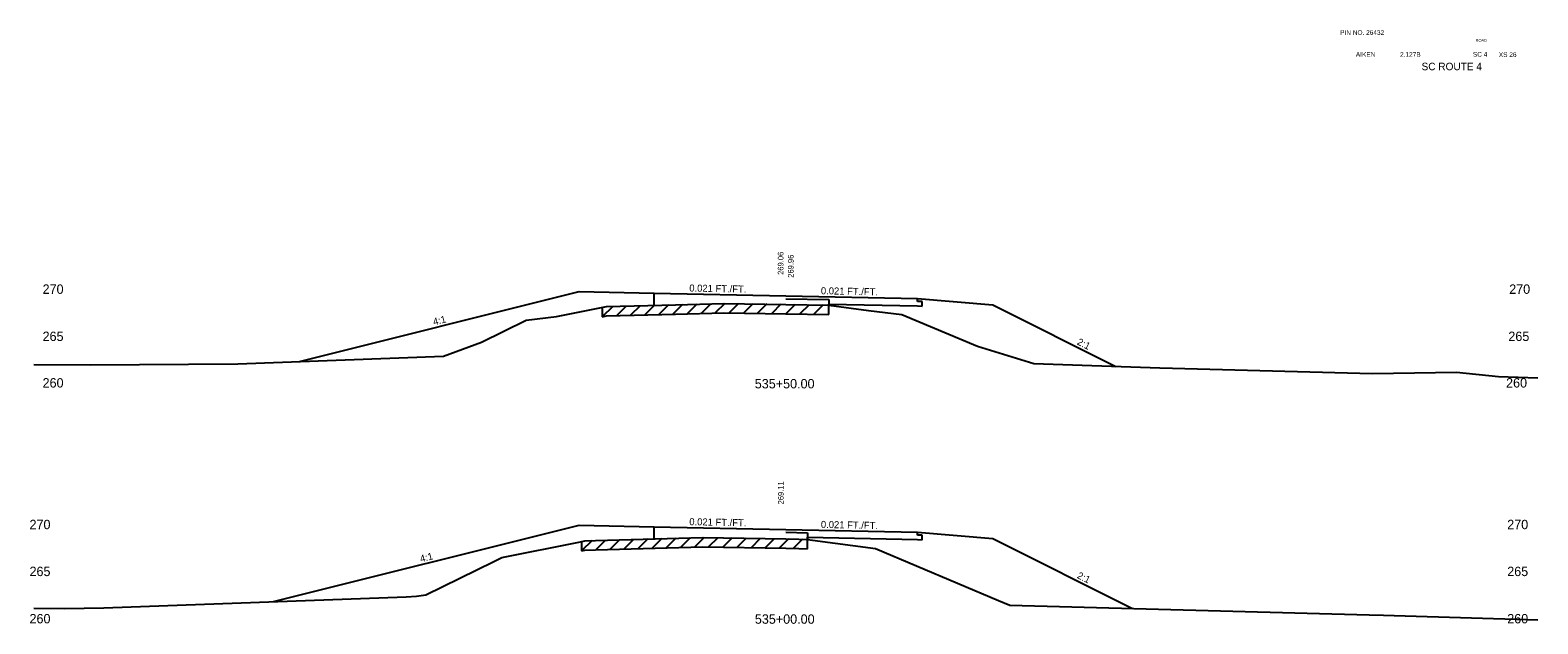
# Model space of a CAD drawing. Extents: x 883 to 1160, y 1002 to 4323.
# Drawn here: x 999.6 to 1160, y 3915.1 to 3978.2 of the extents above; entities that cross this region are included whole.
import ezdxf

# ---------------------------------------------------------------- set-up
doc = ezdxf.new("R2010")
doc.units = 0
for name, color, linetype in [('Level 1', 7, 'Continuous'), ('Level 10', 7, 'Continuous'), ('Level 11', 7, 'Continuous'), ('Level 12', 7, 'Continuous'), ('Level 3', 7, 'Continuous'), ('Level 32', 7, 'Continuous'), ('Level 53', 7, 'Continuous'), ('Level 59', 7, 'Continuous'), ('Level 6', 7, 'Continuous'), ('Level 60', 7, 'Continuous'), ('Level 61', 7, 'Continuous'), ('Level 7', 7, 'Continuous')]:
    doc.layers.add(name, color=color, linetype=linetype)

msp = doc.modelspace()

# ---------------------------------------------------------------- linework, layer by layer
at = {"layer": 'Level 11'}
for p, q in [((1066, 3948.96), (1066, 3950.26)), ((1094, 3949.37), (1094, 3949.67)), ((1094.5, 3949.36), (1094, 3949.37)), ((1094.5, 3948.88), (1094.5, 3949.36)), ((1094, 3948.89), (1094.5, 3948.88)), ((1066, 3924.12), (1066, 3925.4)), ((1094, 3924.52), (1094, 3924.82)), ((1094.5, 3924.5), (1094, 3924.52)), ((1094, 3924.04), (1094.5, 3924.02)), ((1094.5, 3924.02), (1094.5, 3924.5))]:
    msp.add_line(p, q, dxfattribs=at)
at = {"layer": 'Level 12'}
for p, q in [((1084.57, 3948.99), (1084.57, 3949.09)), ((1084.57, 3949.09), (1094, 3948.89)), ((1082.31, 3924.06), (1082.31, 3924.28)), ((1082.31, 3924.28), (1094, 3924.04))]:
    msp.add_line(p, q, dxfattribs=at)
at = {"layer": 'Level 53'}
for p, q in [((1080, 3949.66), (1084.57, 3949.57)), ((1084.57, 3949.57), (1084.57, 3948.99)), ((1080, 3924.81), (1082.31, 3924.76)), ((1082.31, 3924.76), (1082.31, 3924.06))]:
    msp.add_line(p, q, dxfattribs=at)
at = {"layer": 'Level 59'}
for p, q in [((1066, 3950.26), (1080, 3949.96)), ((1080, 3949.96), (1094, 3949.67)), ((1066, 3925.4), (1080, 3925.11)), ((1080, 3925.11), (1094, 3924.82))]:
    msp.add_line(p, q, dxfattribs=at)
at = {"layer": 'Level 6'}
for p, q in [((1058, 3950.42), (1066, 3950.26)), ((1094, 3949.67), (1102, 3949.01)), ((1058, 3925.56), (1066, 3925.4)), ((1094, 3924.82), (1102, 3924.15))]:
    msp.add_line(p, q, dxfattribs=at)
at = {"layer": 'Level 60'}
for p, q in [((1068.25, 3949.02), (1073.41, 3949.17)), ((1073.41, 3949.17), (1080, 3949.06)), ((1052.38, 3947.37), (1055.59, 3947.76)), ((1055.59, 3947.76), (1060.9, 3948.83)), ((1060.9, 3948.83), (1068.25, 3949.02)), ((1080, 3949.06), (1084.58, 3948.99)), ((1084.58, 3948.99), (1088.78, 3948.42)), ((1088.78, 3948.42), (1092.35, 3947.98)), ((1092.35, 3947.98), (1100.37, 3944.61)), ((1047.62, 3945.05), (1052.38, 3947.37)), ((1043.56, 3943.55), (1047.62, 3945.05)), ((1100.37, 3944.61), (1106.37, 3942.77)), ((1000, 3942.67), (1006, 3942.62)), ((1006, 3942.62), (1021.69, 3942.75)), ((1021.69, 3942.75), (1043.56, 3943.55)), ((1106.37, 3942.77), (1119.78, 3942.3)), ((1119.78, 3942.3), (1142.41, 3941.69)), ((1142.41, 3941.69), (1151.34, 3941.83)), ((1151.34, 3941.83), (1155.83, 3941.38)), ((1155.83, 3941.38), (1160, 3941.26)), ((1049.78, 3922.12), (1057.99, 3923.76)), ((1057.99, 3923.76), (1058.6, 3923.91)), ((1058.6, 3923.91), (1059.73, 3923.95)), ((1059.73, 3923.95), (1071.18, 3924.26)), ((1071.18, 3924.26), (1080, 3924.11)), ((1080, 3924.11), (1081.39, 3924.08)), ((1081.39, 3924.08), (1082.3, 3924.06)), ((1082.3, 3924.06), (1082.84, 3923.98)), ((1082.84, 3923.98), (1089.55, 3923.07)), ((1048.93, 3921.7), (1049.78, 3922.12)), ((1089.55, 3923.07), (1102.62, 3917.57)), ((1041.68, 3918.17), (1048.93, 3921.7)), ((1007.44, 3916.77), (1039.6, 3917.96)), ((1039.6, 3917.96), (1040.69, 3918.01)), ((1040.69, 3918.01), (1041.68, 3918.17)), ((1102.62, 3917.57), (1103.84, 3917.05)), ((1103.84, 3917.05), (1142.07, 3916.04)), ((1000, 3916.73), (1003.26, 3916.71)), ((1003.26, 3916.71), (1007.44, 3916.77)), ((1142.07, 3916.04), (1143.58, 3915.98)), ((1143.58, 3915.98), (1144.72, 3915.97)), ((1144.72, 3915.97), (1160, 3915.51))]:
    msp.add_line(p, q, dxfattribs=at)
at = {"layer": 'Level 61'}
for p, q in [((1070.51, 3949.09), (1069.48, 3948.06)), ((1072.01, 3949.13), (1070.98, 3948.1)), ((1073.51, 3949.17), (1072.48, 3948.15)), ((1074.97, 3949.15), (1073.98, 3948.16)), ((1076.47, 3949.12), (1075.49, 3948.14)), ((1077.97, 3949.1), (1076.99, 3948.11)), ((1079.47, 3949.07), (1078.49, 3948.09)), ((1061.58, 3948.84), (1060.47, 3947.74)), ((1060.47, 3948.74), (1060.47, 3947.74)), ((1060.47, 3947.74), (1060.9, 3947.83)), ((1060.9, 3947.83), (1068.25, 3948.02)), ((1063, 3948.88), (1061.97, 3947.85)), ((1064.5, 3948.92), (1063.48, 3947.9)), ((1066.01, 3948.96), (1064.98, 3947.94)), ((1067.51, 3949), (1066.48, 3947.98)), ((1069.01, 3949.05), (1067.98, 3948.02)), ((1068.25, 3948.02), (1073.41, 3948.17)), ((1073.41, 3948.17), (1080, 3948.06)), ((1080.97, 3949.04), (1079.99, 3948.06)), ((1080, 3948.06), (1084.57, 3947.99)), ((1082.48, 3949.02), (1081.49, 3948.04)), ((1083.98, 3949), (1082.99, 3948.01)), ((1084.57, 3947.99), (1084.57, 3948.99)), ((1059.38, 3923.94), (1058.27, 3922.83)), ((1058.27, 3923.83), (1058.27, 3922.83)), ((1060.8, 3923.98), (1059.77, 3922.95)), ((1062.3, 3924.02), (1061.27, 3922.99)), ((1063.8, 3924.06), (1062.77, 3923.03)), ((1065.3, 3924.1), (1064.27, 3923.07)), ((1066.8, 3924.14), (1065.77, 3923.11)), ((1068.3, 3924.18), (1067.28, 3923.15)), ((1069.81, 3924.22), (1068.78, 3923.19)), ((1071.3, 3924.26), (1070.28, 3923.24)), ((1072.76, 3924.23), (1071.78, 3923.25)), ((1074.27, 3924.21), (1073.28, 3923.22)), ((1075.77, 3924.18), (1074.78, 3923.2)), ((1077.27, 3924.15), (1076.29, 3923.17)), ((1078.77, 3924.13), (1077.79, 3923.15)), ((1080.27, 3924.1), (1079.29, 3923.12)), ((1081.77, 3924.07), (1080.79, 3923.09)), ((1082.31, 3923.06), (1082.31, 3924.06)), ((1058.27, 3922.83), (1058.6, 3922.91)), ((1058.6, 3922.91), (1059.73, 3922.95)), ((1059.73, 3922.95), (1071.18, 3923.26)), ((1071.18, 3923.26), (1080, 3923.11)), ((1080, 3923.11), (1081.39, 3923.08)), ((1081.39, 3923.08), (1082.3, 3923.06)), ((1082.3, 3923.06), (1082.31, 3923.06))]:
    msp.add_line(p, q, dxfattribs=at)
at = {"layer": 'Level 7'}
for p, q in [((1028.27, 3942.99), (1058, 3950.42)), ((1102, 3949.01), (1115.09, 3942.46)), ((1025.5, 3917.44), (1058, 3925.56)), ((1102, 3924.15), (1116.89, 3916.7))]:
    msp.add_line(p, q, dxfattribs=at)

# ---------------------------------------------------------------- texts
at = {"layer": 'Level 1'}
for s, height, p in [('PIN NO. 26432', 0.5, (1138.97, 3977.73)), ('AIKEN', 0.5, (1140.64, 3975.41)), (' 2.127B', 0.5, (1145.15, 3975.41)), ('SC ROUTE 4', 0.8, (1147.63, 3973.97)), ('SC 4', 0.5, (1153.09, 3975.41)), ('XS 26', 0.5, (1155.85, 3975.38)), ('535+50.00', 1, (1076.69, 3940.12)), ('535+00.00', 1, (1076.7, 3915.08))]:
    msp.add_text(s, height=height, dxfattribs=at).set_placement(p)
at = {"layer": 'Level 10'}
for s, p in [('269.06', (1079.74, 3952.2)), ('269.11', (1079.76, 3927.78))]:
    msp.add_text(s, height=0.6, rotation=90, dxfattribs=at).set_placement(p)
at = {"layer": 'Level 3'}
for s, height, p in [('ROAD', 0.3, (1153.38, 3977)), (' 270', 1, (1000.55, 3950.18)), (' 270', 1, (1156.58, 3950.18)), (' 265', 1, (1000.55, 3945.16)), (' 265', 1, (1156.49, 3945.16)), (' 260', 1, (1000.55, 3940.21)), (' 260', 1, (1156.25, 3940.21)), (' 270', 1, (999.16, 3925.14)), (' 270', 1, (1156.37, 3925.14)), (' 265', 1, (999.16, 3920.15)), (' 265', 1, (1156.37, 3920.15)), (' 260', 1, (999.16, 3915.12)), (' 260', 1, (1156.37, 3915.12))]:
    msp.add_text(s, height=height, dxfattribs=at).set_placement(p)
at = {"layer": 'Level 32'}
for s, rotation, p in [('0.021 FT./FT.', 358.8084, (1069.72, 3950.43)), ('0.021 FT./FT.', 358.8084, (1083.72, 3950.14)), ('4:1', 14.0362, (1042.56, 3946.82)), ('2:1', 333.435, (1110.91, 3944.83)), ('0.021 FT./FT.', 358.8084, (1069.72, 3925.57)), ('0.021 FT./FT.', 358.8084, (1083.72, 3925.28)), ('4:1', 14.0362, (1041.17, 3921.61)), ('2:1', 333.435, (1110.91, 3919.97))]:
    msp.add_text(s, height=0.75, rotation=rotation, dxfattribs=at).set_placement(p)
at = {"layer": 'Level 59'}
msp.add_text(' 269.96', height=0.6, rotation=90, dxfattribs=at).set_placement((1080.82, 3951.67))

doc.saveas('drawing.dxf')
